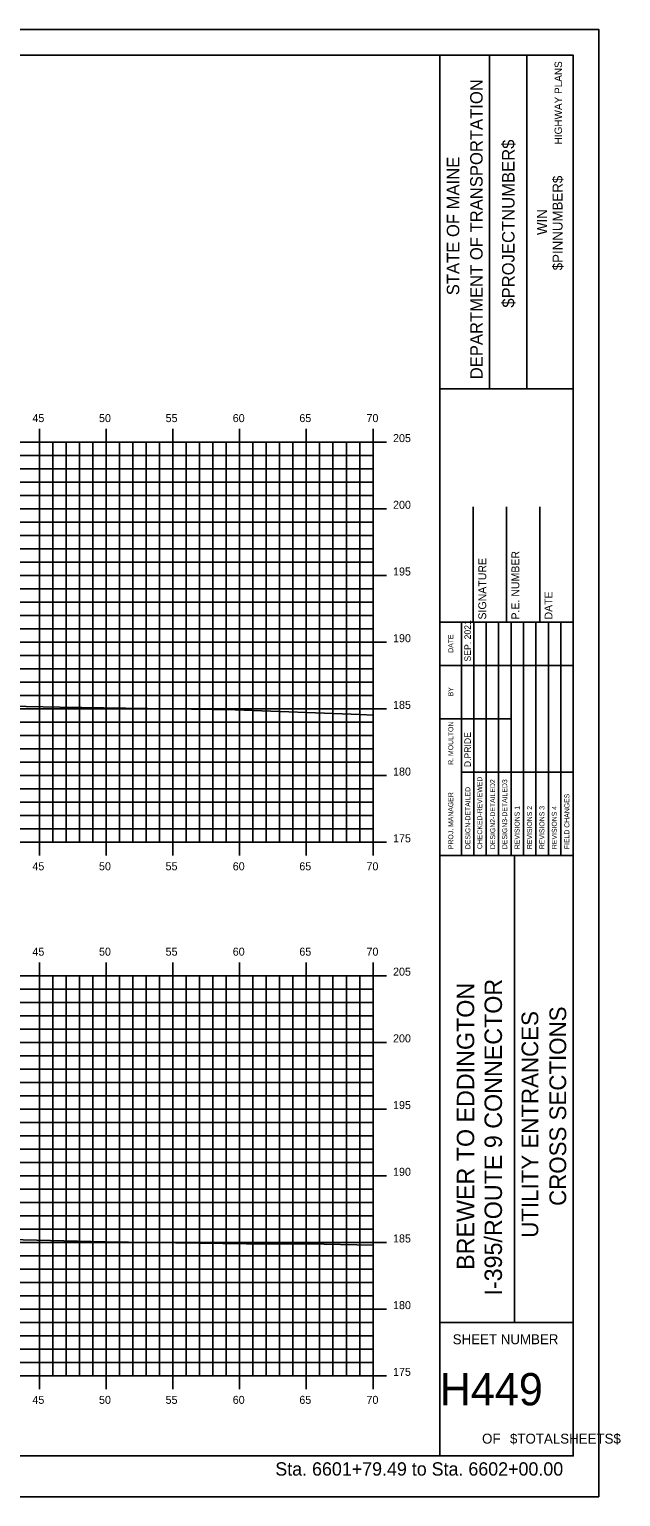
# Model space of a CAD drawing. Extents: x 1723961 to 1724133, y 459560 to 459670.
# Drawn here: x 1724088.7 to 1724133, y 459559.6 to 459669.6 of the extents above; entities that cross this region are included whole.
import ezdxf

# ---------------------------------------------------------------- set-up
doc = ezdxf.new("R2010")
doc.units = 0
for name, color, linetype in [('BORDER', 7, 'Continuous'), ('H_V ANNOTATION', 7, 'Continuous'), ('HIGHWAY_TITLE', 7, 'Continuous'), ('MAJOR', 7, 'Continuous'), ('MINOR', 7, 'Continuous'), ('PLOT BOUNDARY', 7, 'Continuous'), ('S_Roadway_Centerline', 7, 'Continuous')]:
    doc.layers.add(name, color=color, linetype=linetype)

msp = doc.modelspace()

# ---------------------------------------------------------------- linework, layer by layer
at = {"layer": 'BORDER'}
for p, q in [((1724119.47, 459562.61), (1724119.47, 459667.61)), ((1724123.2, 459642.61), (1724123.2, 459667.61)), ((1724126, 459642.61), (1724126, 459667.61)), ((1724119.47, 459642.61), (1724129.47, 459642.61)), ((1724121.97, 459625.12), (1724121.97, 459633.76)), ((1724124.47, 459625.12), (1724124.47, 459633.76)), ((1724126.97, 459625.12), (1724126.97, 459633.76)), ((1724119.47, 459625.12), (1724129.47, 459625.12)), ((1724119.47, 459607.62), (1724129.47, 459607.62)), ((1724125.06, 459572.62), (1724125.06, 459607.62)), ((1724119.47, 459572.62), (1724129.47, 459572.62))]:
    msp.add_line(p, q, dxfattribs=at)
msp.add_lwpolyline([(1723969.47, 459562.61), (1724129.47, 459562.61), (1724129.47, 459667.61), (1723969.47, 459667.61)], close=True, dxfattribs=at)
for points in [[(1724121.09, 459621.87), (1724121.09, 459625.12)], [(1724122.02, 459607.62), (1724122.02, 459625.12)], [(1724122.95, 459625.12), (1724122.95, 459607.62)], [(1724123.88, 459607.62), (1724123.88, 459625.12)], [(1724124.82, 459607.62), (1724124.82, 459625.12)], [(1724125.75, 459607.62), (1724125.75, 459625.12)], [(1724126.68, 459607.62), (1724126.68, 459625.12)], [(1724127.61, 459607.62), (1724127.61, 459625.12)], [(1724128.54, 459607.62), (1724128.54, 459625.12)], [(1724121.09, 459607.62), (1724121.09, 459624.41)], [(1724119.47, 459621.87), (1724129.47, 459621.87)], [(1724119.47, 459617.87), (1724121.09, 459617.87)], [(1724121.09, 459617.87), (1724124.81, 459617.87)], [(1724121.09, 459613.87), (1724129.47, 459613.87)]]:
    msp.add_lwpolyline(points, dxfattribs=at)
at = {"layer": 'MAJOR'}
for p, q in [((1724089.47, 459639.61), (1724089.47, 459638.61)), ((1724094.47, 459639.61), (1724094.47, 459638.61)), ((1724099.47, 459639.61), (1724099.47, 459638.61)), ((1724104.47, 459639.61), (1724104.47, 459638.61)), ((1724109.47, 459639.61), (1724109.47, 459638.61)), ((1724114.47, 459639.61), (1724114.47, 459638.61)), ((1723974.47, 459638.61), (1724114.47, 459638.61)), ((1723974.47, 459638.61), (1724114.47, 459638.61)), ((1724089.47, 459608.61), (1724089.47, 459638.61)), ((1724094.47, 459608.61), (1724094.47, 459638.61)), ((1724099.47, 459608.61), (1724099.47, 459638.61)), ((1724104.47, 459608.61), (1724104.47, 459638.61)), ((1724109.47, 459608.61), (1724109.47, 459638.61)), ((1724115.48, 459638.61), (1724113.47, 459638.61)), ((1724114.47, 459608.61), (1724114.47, 459638.61)), ((1724114.47, 459608.61), (1724114.47, 459638.61)), ((1723974.47, 459633.61), (1724114.47, 459633.61)), ((1724115.48, 459633.61), (1724113.47, 459633.61)), ((1723974.47, 459628.61), (1724114.47, 459628.61)), ((1724115.48, 459628.61), (1724113.47, 459628.61)), ((1723974.47, 459623.61), (1724114.47, 459623.61)), ((1724115.48, 459623.61), (1724113.47, 459623.61)), ((1723974.47, 459618.61), (1724114.47, 459618.61)), ((1724115.48, 459618.61), (1724113.47, 459618.61)), ((1723974.47, 459613.61), (1724114.47, 459613.61)), ((1724115.48, 459613.61), (1724113.47, 459613.61)), ((1723974.47, 459608.61), (1724114.47, 459608.61)), ((1723974.47, 459608.61), (1724114.47, 459608.61)), ((1724089.47, 459607.61), (1724089.47, 459608.61)), ((1724094.47, 459607.61), (1724094.47, 459608.61)), ((1724099.47, 459607.61), (1724099.47, 459608.61)), ((1724104.47, 459607.61), (1724104.47, 459608.61)), ((1724109.47, 459607.61), (1724109.47, 459608.61)), ((1724115.48, 459608.61), (1724113.47, 459608.61)), ((1724114.47, 459607.61), (1724114.47, 459608.61)), ((1724089.47, 459599.61), (1724089.47, 459598.61)), ((1724094.47, 459599.61), (1724094.47, 459598.61)), ((1724099.47, 459599.61), (1724099.47, 459598.61)), ((1724104.47, 459599.61), (1724104.47, 459598.61)), ((1724109.47, 459599.61), (1724109.47, 459598.61)), ((1724114.47, 459599.61), (1724114.47, 459598.61)), ((1723974.47, 459598.61), (1724114.47, 459598.61)), ((1723974.47, 459598.61), (1724114.47, 459598.61)), ((1724089.47, 459568.61), (1724089.47, 459598.61)), ((1724094.47, 459568.61), (1724094.47, 459598.61)), ((1724099.47, 459568.61), (1724099.47, 459598.61)), ((1724104.47, 459568.61), (1724104.47, 459598.61)), ((1724109.47, 459568.61), (1724109.47, 459598.61)), ((1724115.48, 459598.61), (1724113.47, 459598.61)), ((1724114.47, 459568.61), (1724114.47, 459598.61)), ((1724114.47, 459568.61), (1724114.47, 459598.61)), ((1723974.47, 459593.61), (1724114.47, 459593.61)), ((1724115.48, 459593.61), (1724113.47, 459593.61)), ((1723974.47, 459588.61), (1724114.47, 459588.61)), ((1724115.48, 459588.61), (1724113.47, 459588.61)), ((1723974.47, 459583.61), (1724114.47, 459583.61)), ((1724115.48, 459583.61), (1724113.47, 459583.61)), ((1723974.47, 459578.61), (1724114.47, 459578.61)), ((1724115.48, 459578.61), (1724113.47, 459578.61)), ((1723974.47, 459573.61), (1724114.47, 459573.61)), ((1724115.48, 459573.61), (1724113.47, 459573.61)), ((1723974.47, 459568.61), (1724114.47, 459568.61)), ((1723974.47, 459568.61), (1724114.47, 459568.61)), ((1724089.47, 459567.61), (1724089.47, 459568.61)), ((1724094.47, 459567.61), (1724094.47, 459568.61)), ((1724099.47, 459567.61), (1724099.47, 459568.61)), ((1724104.47, 459567.61), (1724104.47, 459568.61)), ((1724109.47, 459567.61), (1724109.47, 459568.61)), ((1724115.48, 459568.61), (1724113.47, 459568.61)), ((1724114.47, 459567.61), (1724114.47, 459568.61))]:
    msp.add_line(p, q, dxfattribs=at)
at = {"layer": 'MINOR'}
for p, q in [((1724090.47, 459608.61), (1724090.47, 459638.61)), ((1724091.47, 459608.61), (1724091.47, 459638.61)), ((1724092.47, 459608.61), (1724092.47, 459638.61)), ((1724093.47, 459608.61), (1724093.47, 459638.61)), ((1724095.47, 459608.61), (1724095.47, 459638.61)), ((1724096.47, 459608.61), (1724096.47, 459638.61)), ((1724097.47, 459608.61), (1724097.47, 459638.61)), ((1724098.47, 459608.61), (1724098.47, 459638.61)), ((1724100.47, 459608.61), (1724100.47, 459638.61)), ((1724101.47, 459608.61), (1724101.47, 459638.61)), ((1724102.47, 459608.61), (1724102.47, 459638.61)), ((1724103.47, 459608.61), (1724103.47, 459638.61)), ((1724105.47, 459608.61), (1724105.47, 459638.61)), ((1724106.47, 459608.61), (1724106.47, 459638.61)), ((1724107.47, 459608.61), (1724107.47, 459638.61)), ((1724108.47, 459608.61), (1724108.47, 459638.61)), ((1724110.47, 459608.61), (1724110.47, 459638.61)), ((1724111.47, 459608.61), (1724111.47, 459638.61)), ((1724112.47, 459608.61), (1724112.47, 459638.61)), ((1724113.47, 459608.61), (1724113.47, 459638.61)), ((1723974.47, 459637.61), (1724114.47, 459637.61)), ((1724114.47, 459637.61), (1724113.47, 459637.61)), ((1723974.47, 459636.61), (1724114.47, 459636.61)), ((1724114.47, 459636.61), (1724113.47, 459636.61)), ((1723974.47, 459635.61), (1724114.47, 459635.61)), ((1724114.47, 459635.61), (1724113.47, 459635.61)), ((1723974.47, 459634.61), (1724114.47, 459634.61)), ((1724114.47, 459634.61), (1724113.47, 459634.61)), ((1723974.47, 459632.61), (1724114.47, 459632.61)), ((1724114.47, 459632.61), (1724113.47, 459632.61)), ((1723974.47, 459631.61), (1724114.47, 459631.61)), ((1723974.47, 459630.61), (1724114.47, 459630.61)), ((1724114.47, 459631.61), (1724113.47, 459631.61)), ((1724114.47, 459630.61), (1724113.47, 459630.61)), ((1723974.47, 459629.61), (1724114.47, 459629.61)), ((1724114.47, 459629.61), (1724113.47, 459629.61)), ((1723974.47, 459627.61), (1724114.47, 459627.61)), ((1724114.47, 459627.61), (1724113.47, 459627.61)), ((1723974.47, 459626.61), (1724114.47, 459626.61)), ((1724114.47, 459626.61), (1724113.47, 459626.61)), ((1723974.47, 459625.61), (1724114.47, 459625.61)), ((1724114.47, 459625.61), (1724113.47, 459625.61)), ((1723974.47, 459624.61), (1724114.47, 459624.61)), ((1724114.47, 459624.61), (1724113.47, 459624.61)), ((1723974.47, 459622.61), (1724114.47, 459622.61)), ((1724114.47, 459622.61), (1724113.47, 459622.61)), ((1723974.47, 459621.61), (1724114.47, 459621.61)), ((1724114.47, 459621.61), (1724113.47, 459621.61)), ((1723974.47, 459620.61), (1724114.47, 459620.61)), ((1723974.47, 459619.61), (1724114.47, 459619.61)), ((1724114.47, 459620.61), (1724113.47, 459620.61)), ((1724114.47, 459619.61), (1724113.47, 459619.61)), ((1723974.47, 459617.61), (1724114.47, 459617.61)), ((1724114.47, 459617.61), (1724113.47, 459617.61)), ((1723974.47, 459616.61), (1724114.47, 459616.61)), ((1724114.47, 459616.61), (1724113.47, 459616.61)), ((1723974.47, 459615.61), (1724114.47, 459615.61)), ((1724114.47, 459615.61), (1724113.47, 459615.61)), ((1723974.47, 459614.61), (1724114.47, 459614.61)), ((1724114.47, 459614.61), (1724113.47, 459614.61)), ((1723974.47, 459612.61), (1724114.47, 459612.61)), ((1724114.47, 459612.61), (1724113.47, 459612.61)), ((1723974.47, 459611.61), (1724114.47, 459611.61)), ((1724114.47, 459611.61), (1724113.47, 459611.61)), ((1723974.47, 459610.61), (1724114.47, 459610.61)), ((1724114.47, 459610.61), (1724113.47, 459610.61)), ((1723974.47, 459609.61), (1724114.47, 459609.61)), ((1724114.47, 459609.61), (1724113.47, 459609.61)), ((1723974.47, 459597.61), (1724114.47, 459597.61)), ((1724090.47, 459568.61), (1724090.47, 459598.61)), ((1724091.47, 459568.61), (1724091.47, 459598.61)), ((1724092.47, 459568.61), (1724092.47, 459598.61)), ((1724093.47, 459568.61), (1724093.47, 459598.61)), ((1724095.47, 459568.61), (1724095.47, 459598.61)), ((1724096.47, 459568.61), (1724096.47, 459598.61)), ((1724097.47, 459568.61), (1724097.47, 459598.61)), ((1724098.47, 459568.61), (1724098.47, 459598.61)), ((1724100.47, 459568.61), (1724100.47, 459598.61)), ((1724101.47, 459568.61), (1724101.47, 459598.61)), ((1724102.47, 459568.61), (1724102.47, 459598.61)), ((1724103.47, 459568.61), (1724103.47, 459598.61)), ((1724105.47, 459568.61), (1724105.47, 459598.61)), ((1724106.47, 459568.61), (1724106.47, 459598.61)), ((1724107.47, 459568.61), (1724107.47, 459598.61)), ((1724108.47, 459568.61), (1724108.47, 459598.61)), ((1724110.47, 459568.61), (1724110.47, 459598.61)), ((1724111.47, 459568.61), (1724111.47, 459598.61)), ((1724112.47, 459568.61), (1724112.47, 459598.61)), ((1724113.47, 459568.61), (1724113.47, 459598.61)), ((1724114.47, 459597.61), (1724113.47, 459597.61)), ((1723974.47, 459596.61), (1724114.47, 459596.61)), ((1724114.47, 459596.61), (1724113.47, 459596.61)), ((1723974.47, 459595.61), (1724114.47, 459595.61)), ((1724114.47, 459595.61), (1724113.47, 459595.61)), ((1723974.47, 459594.61), (1724114.47, 459594.61)), ((1724114.47, 459594.61), (1724113.47, 459594.61)), ((1723974.47, 459592.61), (1724114.47, 459592.61)), ((1724114.47, 459592.61), (1724113.47, 459592.61)), ((1723974.47, 459591.61), (1724114.47, 459591.61)), ((1724114.47, 459591.61), (1724113.47, 459591.61)), ((1723974.47, 459590.61), (1724114.47, 459590.61)), ((1724114.47, 459590.61), (1724113.47, 459590.61)), ((1723974.47, 459589.61), (1724114.47, 459589.61)), ((1724114.47, 459589.61), (1724113.47, 459589.61)), ((1723974.47, 459587.61), (1724114.47, 459587.61)), ((1723974.47, 459586.61), (1724114.47, 459586.61)), ((1724114.47, 459587.61), (1724113.47, 459587.61)), ((1724114.47, 459586.61), (1724113.47, 459586.61)), ((1723974.47, 459585.61), (1724114.47, 459585.61)), ((1724114.47, 459585.61), (1724113.47, 459585.61)), ((1723974.47, 459584.61), (1724114.47, 459584.61)), ((1724114.47, 459584.61), (1724113.47, 459584.61)), ((1723974.47, 459582.61), (1724114.47, 459582.61)), ((1724114.47, 459582.61), (1724113.47, 459582.61)), ((1723974.47, 459581.61), (1724114.47, 459581.61)), ((1724114.47, 459581.61), (1724113.47, 459581.61)), ((1723974.47, 459580.61), (1724114.47, 459580.61)), ((1724114.47, 459580.61), (1724113.47, 459580.61)), ((1723974.47, 459579.61), (1724114.47, 459579.61)), ((1724114.47, 459579.61), (1724113.47, 459579.61)), ((1723974.47, 459577.61), (1724114.47, 459577.61)), ((1724114.47, 459577.61), (1724113.47, 459577.61)), ((1723974.47, 459576.61), (1724114.47, 459576.61)), ((1723974.47, 459575.61), (1724114.47, 459575.61)), ((1724114.47, 459576.61), (1724113.47, 459576.61)), ((1724114.47, 459575.61), (1724113.47, 459575.61)), ((1723974.47, 459574.61), (1724114.47, 459574.61)), ((1724114.47, 459574.61), (1724113.47, 459574.61)), ((1723974.47, 459572.61), (1724114.47, 459572.61)), ((1724114.47, 459572.61), (1724113.47, 459572.61)), ((1723974.47, 459571.61), (1724114.47, 459571.61)), ((1724114.47, 459571.61), (1724113.47, 459571.61)), ((1723974.47, 459570.61), (1724114.47, 459570.61)), ((1724114.47, 459570.61), (1724113.47, 459570.61)), ((1723974.47, 459569.61), (1724114.47, 459569.61)), ((1724114.47, 459569.61), (1724113.47, 459569.61))]:
    msp.add_line(p, q, dxfattribs=at)
at = {"layer": 'PLOT BOUNDARY'}
msp.add_lwpolyline([(1723961.38, 459559.55), (1724131.38, 459559.55), (1724131.38, 459669.55), (1723961.38, 459669.55)], close=True, dxfattribs=at)
at = {"layer": 'S_Roadway_Centerline'}
for points in [[(1723974.47, 459622.03), (1723980.84, 459621.98), (1723993.04, 459621.63), (1724003.85, 459620.76), (1724003.88, 459620.76), (1724016.2, 459620.8), (1724025.64, 459620.62), (1724029.82, 459620.46), (1724046.7, 459619.91), (1724055.65, 459619.73), (1724062.61, 459619.53), (1724079.62, 459618.91), (1724085.94, 459618.83), (1724091.01, 459618.73), (1724104.13, 459618.53), (1724113.51, 459618.18), (1724114.47, 459618.14)], [(1723974.47, 459582.67), (1723975.57, 459582.63), (1723981.88, 459582.17), (1723988.93, 459581.99), (1723994.93, 459581.86), (1724001.47, 459581.65), (1724009.84, 459581.51), (1724028.66, 459580.69), (1724030.53, 459580.58), (1724048.38, 459580.09), (1724051.97, 459579.99), (1724052.88, 459579.98), (1724072.14, 459579.63), (1724078.31, 459579.39), (1724087.23, 459578.82), (1724094.37, 459578.66), (1724105, 459578.51), (1724110.8, 459578.47), (1724114.47, 459578.4)]]:
    msp.add_lwpolyline(points, dxfattribs=at)

# ---------------------------------------------------------------- texts
at = {"layer": 'BORDER'}
for s, height, p in [('DEPARTMENT OF TRANSPORTATION', 0.9318, (1724122.68, 459643.32)), ('$PROJECTNUMBER$', 0.9318, (1724125.07, 459648.69)), ('STATE OF MAINE', 0.9318, (1724120.93, 459649.62)), ('$PINNUMBER$', 0.7453, (1724128.67, 459651.49)), ('WIN', 0.745, (1724127.51, 459654.14)), ('SIGNATURE', 0.591, (1724122.95, 459625.31)), ('P.E. NUMBER', 0.5906, (1724125.43, 459625.31)), ('DATE', 0.591, (1724127.91, 459625.31)), ('SEP. 2021', 0.485, (1724121.8, 459622.16)), ('DATE', 0.371, (1724120.48, 459622.82)), ('BY', 0.371, (1724120.48, 459619.55)), ('R. MOULTON', 0.373, (1724120.48, 459614.42)), ('D.PRIDE', 0.485, (1724121.8, 459614.24)), ('CHECKED-REVIEWED', 0.3727, (1724122.65, 459608.1)), ('DESIGN2-DETAILED2', 0.3727, (1724123.62, 459608.1)), ('DESIGN3-DETAILED3', 0.3727, (1724124.52, 459608.1)), ('PROJ. MANAGER', 0.3727, (1724120.48, 459608.1)), ('DESIGN-DETAILED', 0.3727, (1724121.76, 459608.1)), ('FIELD CHANGES', 0.3727, (1724129.18, 459608.1)), ('REVISIONS 1', 0.3727, (1724125.45, 459608.1)), ('REVISIONS 2', 0.3727, (1724126.38, 459608.1)), ('REVISIONS 3', 0.3727, (1724127.31, 459608.1)), ('REVISIONS 4', 0.3727, (1724128.24, 459608.1)), ('UTILITY ENTRANCES', 1.25, (1724126.85, 459578.96)), ('CROSS SECTIONS', 1.25, (1724128.94, 459581.35))]:
    msp.add_text(s, height=height, rotation=90, dxfattribs=at).set_placement(p)
for s, height, p in [('SHEET NUMBER', 0.7453, (1724120.44, 459570.98)), ('H449', 2.419, (1724119.46, 459566.4)), ('OF', 0.745, (1724122.64, 459563.53)), ('$TOTALSHEETS$', 0.7453, (1724124.73, 459563.53))]:
    msp.add_text(s, height=height, dxfattribs=at).set_placement(p)
at = {"layer": 'H_V ANNOTATION'}
for s, height, p in [('45', 0.6, (1724088.95, 459640.11)), ('50', 0.6, (1724093.94, 459640.11)), ('55', 0.6, (1724098.93, 459640.11)), ('60', 0.6, (1724103.96, 459640.11)), ('65', 0.6, (1724108.95, 459640.11)), ('70', 0.6, (1724113.98, 459640.11)), ('205', 0.6, (1724115.97, 459638.61)), ('200', 0.6, (1724115.97, 459633.61)), ('195', 0.6, (1724115.97, 459628.61)), ('190', 0.6, (1724115.97, 459623.61)), ('185', 0.6, (1724115.97, 459618.61)), ('180', 0.6, (1724115.97, 459613.61)), ('175', 0.6, (1724115.97, 459608.61)), ('45', 0.6, (1724088.95, 459606.51)), ('50', 0.6, (1724093.94, 459606.51)), ('55', 0.6, (1724098.93, 459606.51)), ('60', 0.6, (1724103.96, 459606.51)), ('65', 0.6, (1724108.95, 459606.51)), ('70', 0.6, (1724113.98, 459606.51)), ('45', 0.6, (1724088.95, 459600.11)), ('50', 0.6, (1724093.94, 459600.11)), ('55', 0.6, (1724098.93, 459600.11)), ('60', 0.6, (1724103.96, 459600.11)), ('65', 0.6, (1724108.95, 459600.11)), ('70', 0.6, (1724113.98, 459600.11)), ('205', 0.6, (1724115.97, 459598.61)), ('200', 0.6, (1724115.97, 459593.61)), ('195', 0.6, (1724115.97, 459588.61)), ('190', 0.6, (1724115.97, 459583.61)), ('185', 0.6, (1724115.97, 459578.61)), ('180', 0.6, (1724115.97, 459573.61)), ('175', 0.6, (1724115.97, 459568.61)), ('45', 0.6, (1724088.95, 459566.51)), ('50', 0.6, (1724093.94, 459566.51)), ('55', 0.6, (1724098.93, 459566.51)), ('60', 0.6, (1724103.96, 459566.51)), ('65', 0.6, (1724108.95, 459566.51)), ('70', 0.6, (1724113.98, 459566.51)), ('Sta. 6601+79.49 to Sta. 6602+00.00', 1.0002, (1724107.15, 459561.13))]:
    msp.add_text(s, height=height, dxfattribs=at).set_placement(p)
at = {"layer": 'HIGHWAY_TITLE'}
for s, height, p in [('HIGHWAY PLANS', 0.559, (1724128.63, 459660.93)), ('BREWER TO EDDINGTON', 1.3043, (1724122.05, 459576.56)), ('I-395/ROUTE 9 CONNECTOR', 1.3043, (1724124.13, 459574.63))]:
    msp.add_text(s, height=height, rotation=90, dxfattribs=at).set_placement(p)

doc.saveas('drawing.dxf')
